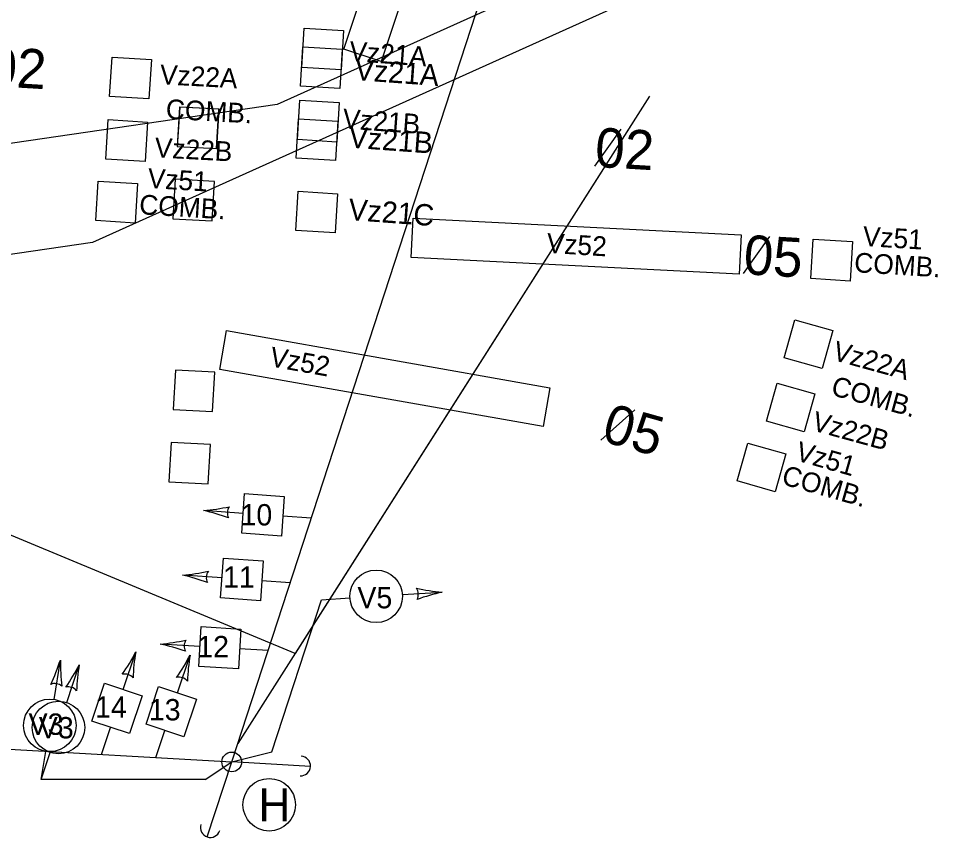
# Model space of a CAD drawing. Extents: x 647787 to 668496, y 640478 to 654412.
# Drawn here: x 662097 to 662238.5, y 647220.2 to 647344.8 of the extents above; entities that cross this region are included whole.
import ezdxf

# ---------------------------------------------------------------- set-up
doc = ezdxf.new("R2010")
doc.units = 0
for name, color, linetype in [('Default', 7, 'Continuous'), ('TEMP_DETECTION ZONE_Stage 2', 7, 'Continuous'), ('TEMP_DETECTION ZONE_STAGE 3', 7, 'Continuous'), ('TEMP_DETECTION_ZONE_STAGE 4', 7, 'Continuous'), ('TEMP_DETECTION_ZONE_STAGE 5', 7, 'Continuous'), ('TEMP_SIGNAL_HEAD_Stage 3', 7, 'Continuous'), ('TEMP_SIGNAL_HEAD_STAGE4', 7, 'Continuous'), ('TEMP_SIGNAL_POLES_STAGE 1B', 7, 'Continuous'), ('TEMP_SIGNAL_POLES_STAGE 3', 7, 'Continuous'), ('TEMP_SIGNAL_POLES_STAGE 4', 7, 'Continuous'), ('TEXT_TEMP_SIGNAL_POLES_STAGE 3', 7, 'Continuous'), ('TEXT_TEMP_SIGNAL_POLES_STAGE 4', 7, 'Continuous')]:
    doc.layers.add(name, color=color, linetype=linetype)

msp = doc.modelspace()

# ---------------------------------------------------------------- linework, layer by layer
at = {"layer": 'Default'}
for p, q in [((662184.78, 647322.37), (662188.82, 647328.03)), ((662207.42, 647306.03), (662211.46, 647311.69)), ((662185.72, 647280.65), (662190.87, 647285.31))]:
    msp.add_line(p, q, dxfattribs=at)
for points in [[(662536.7, 647412.12), (662361.86, 647433.21), (662136.44, 647331.77)], [(662508.55, 647391.12), (662333.71, 647412.21), (662108.29, 647310.77)], [(662508.55, 647391.12), (662333.71, 647412.21), (662108.29, 647310.77)], [(662508.55, 647391.12), (662333.71, 647412.21), (662108.29, 647310.77)], [(662193.11, 647333.04), (662139.14, 647248.2), (661974.83, 647316.48)], [(662193.11, 647333.04), (662130.42, 647234.5)], [(662193.11, 647333.04), (662130.42, 647234.5)], [(662136.44, 647331.77), (661882.02, 647294.61), (661114.4, 647320.89)], [(662108.29, 647310.77), (661853.87, 647273.61), (661086.25, 647299.89)], [(662108.29, 647310.77), (661888.55, 647278.68)], [(662108.29, 647310.77), (661888.55, 647278.68)]]:
    msp.add_lwpolyline(points, dxfattribs=at)
at = {"layer": 'TEMP_DETECTION ZONE_Stage 2'}
msp.add_line((662115.15, 647319.72), (662114.78, 647313.73), dxfattribs=at)
for points in [[(662116.9, 647332.64), (662110.91, 647333), (662111.28, 647338.99), (662117.26, 647338.63)], [(662116.33, 647323.11), (662110.34, 647323.47), (662110.7, 647329.46), (662116.69, 647329.1)], [(662114.78, 647313.73), (662108.8, 647314.09), (662109.16, 647320.08), (662115.15, 647319.72)]]:
    msp.add_lwpolyline(points, close=True, dxfattribs=at)
at = {"layer": 'TEMP_DETECTION ZONE_STAGE 3'}
for points in [[(662152.25, 647338.3), (662146.56, 647340.2), (662162.39, 647387.63), (662168.08, 647385.73)], [(662121.57, 647331.36), (662121.21, 647325.37), (662127.2, 647325.06), (662127.56, 647331.04)], [(662121.57, 647331.36), (662121.21, 647325.37), (662127.2, 647325.06), (662127.56, 647331.04)], [(662121.57, 647331.36), (662121.21, 647325.37), (662127.2, 647325.06), (662127.56, 647331.04)], [(662121.58, 647331.36), (662121.21, 647325.37), (662127.21, 647325.06), (662127.57, 647331.05)], [(662120.91, 647320.38), (662120.55, 647314.39), (662126.54, 647314.08), (662126.9, 647320.06)], [(662120.91, 647320.38), (662120.55, 647314.39), (662126.54, 647314.08), (662126.9, 647320.06)], [(662120.91, 647320.38), (662120.55, 647314.39), (662126.54, 647314.08), (662126.9, 647320.06)], [(662120.91, 647320.38), (662120.55, 647314.39), (662126.54, 647314.08), (662126.9, 647320.07)], [(662156.83, 647308.46), (662157.14, 647314.45), (662207.07, 647311.91), (662206.77, 647305.92)], [(662223.68, 647304.9), (662217.69, 647305.26), (662218.05, 647311.25), (662224.04, 647310.89)]]:
    msp.add_lwpolyline(points, close=True, dxfattribs=at)
at = {"layer": 'TEMP_DETECTION_ZONE_STAGE 4'}
for points in [[(662219.41, 647291.58), (662213.64, 647293.21), (662215.27, 647298.99), (662221.04, 647297.36)], [(662127.67, 647291.45), (662128.72, 647297.35), (662177.95, 647288.65), (662176.91, 647282.74)], [(662120.95, 647291.32), (662120.59, 647285.33), (662126.58, 647285.02), (662126.94, 647291.01)], [(662120.95, 647291.32), (662120.59, 647285.33), (662126.58, 647285.02), (662126.94, 647291.01)], [(662120.95, 647291.32), (662120.59, 647285.33), (662126.58, 647285.02), (662126.94, 647291.01)], [(662120.95, 647291.32), (662120.59, 647285.33), (662126.58, 647285.02), (662126.94, 647291.01)], [(662216.69, 647281.96), (662210.92, 647283.59), (662212.55, 647289.37), (662218.33, 647287.73)], [(662120.29, 647280.34), (662119.93, 647274.35), (662125.92, 647274.04), (662126.28, 647280.03)], [(662120.29, 647280.34), (662119.93, 647274.35), (662125.92, 647274.04), (662126.28, 647280.03)], [(662120.29, 647280.34), (662119.93, 647274.35), (662125.92, 647274.04), (662126.28, 647280.03)], [(662120.29, 647280.34), (662119.93, 647274.35), (662125.92, 647274.04), (662126.28, 647280.03)], [(662212.25, 647272.83), (662206.47, 647274.46), (662208.1, 647280.23), (662213.88, 647278.6)]]:
    msp.add_lwpolyline(points, close=True, dxfattribs=at)
at = {"layer": 'TEMP_DETECTION_ZONE_STAGE 5'}
for points in [[(662146.15, 647337.04), (662140.16, 647337.4), (662140.52, 647343.39), (662146.51, 647343.03)], [(662145.49, 647326.06), (662139.5, 647326.42), (662139.86, 647332.41), (662145.85, 647332.05)]]:
    msp.add_lwpolyline(points, close=True, dxfattribs=at)
at = {"layer": 'TEMP_SIGNAL_HEAD_Stage 3'}
for p, q in [((662131.24, 647269.53), (662125.21, 647269.96)), ((662141.62, 647268.78), (662137.28, 647269.09)), ((662128.03, 647259.7), (662122, 647260.14)), ((662138.41, 647258.95), (662134.07, 647259.27)), ((662135.62, 647233.21), (662143.19, 647256.39)), ((662124.65, 647249.27), (662118.62, 647249.63)), ((662135.04, 647248.64), (662130.7, 647248.9)), ((662112.97, 647242.71), (662114.89, 647248.44)), ((662121.25, 647242.23), (662123.16, 647247.96)), ((662104.37, 647240.74), (662106.29, 647246.49)), ((662109.68, 647232.84), (662111.05, 647236.96)), ((662117.95, 647232.36), (662119.33, 647236.48)), ((662100.48, 647229.04), (662101.85, 647233.15)), ((662129.5, 647231.69), (662135.62, 647233.21)), ((662125.48, 647229.04), (662129.5, 647231.69)), ((662125.48, 647229.04), (662100.48, 647229.04))]:
    msp.add_line(p, q, dxfattribs=at)
for points in [[(662137.5, 647272.12), (662137.06, 647266.07), (662131.02, 647266.5), (662131.45, 647272.55)], [(662134.29, 647262.29), (662133.86, 647256.24), (662127.81, 647256.68), (662128.25, 647262.73)], [(662130.88, 647251.93), (662130.52, 647245.87), (662124.47, 647246.24), (662124.83, 647252.29)], [(662113.93, 647236), (662108.18, 647237.92), (662110.1, 647243.67), (662115.85, 647241.75)], [(662122.2, 647235.52), (662116.45, 647237.44), (662118.37, 647243.19), (662124.12, 647241.27)]]:
    msp.add_lwpolyline(points, close=True, dxfattribs=at)
msp.add_circle((662103.11, 647236.94), 4, dxfattribs=at)
for centre, radius, start, end in [((662122.91, 647299.35), 29.47, 274.4773, 282.2154), ((662118.71, 647241.22), 29.47, 69.5225, 77.2606), ((662130.46, 647269.59), 1.63, 144.0216, 207.7163), ((662119.7, 647289.52), 29.47, 274.4773, 282.2154), ((662115.5, 647231.39), 29.47, 69.5225, 77.2606), ((662127.26, 647259.76), 1.63, 144.0216, 207.7163), ((662115.97, 647278.98), 29.47, 275.1535, 282.8917), ((662123.88, 647249.31), 1.63, 144.6979, 208.3925), ((662112.46, 647220.81), 29.47, 70.1988, 77.9369), ((662088.64, 647261.85), 29.47, 325.2014, 332.9395), ((662143.92, 647243.4), 29.47, 170.1562, 177.8943), ((662096.91, 647261.37), 29.47, 325.2014, 332.9395), ((662152.2, 647242.92), 29.47, 170.1562, 177.8943), ((662080.03, 647259.87), 29.47, 325.255, 332.9931), ((662135.33, 647241.48), 29.47, 170.2106, 177.9488), ((662113.22, 647243.45), 1.63, 39.7005, 103.3952), ((662121.49, 647242.97), 1.63, 39.7005, 103.3952), ((662104.62, 647241.49), 1.63, 39.744, 103.4386)]:
    msp.add_arc(centre, radius, start, end, dxfattribs=at)
at = {"layer": 'TEMP_SIGNAL_HEAD_STAGE4'}
for p, q in [((662131.24, 647269.53), (662125.21, 647269.96)), ((662141.62, 647268.78), (662137.28, 647269.09)), ((662128.03, 647259.7), (662122, 647260.14)), ((662138.41, 647258.95), (662134.07, 647259.27)), ((662155.49, 647257.16), (662161.55, 647257.53)), ((662135.62, 647233.21), (662143.19, 647256.39)), ((662143.19, 647256.39), (662147.51, 647256.66)), ((662124.65, 647249.27), (662118.62, 647249.63)), ((662135.04, 647248.64), (662130.7, 647248.9)), ((662102.44, 647241.21), (662103.4, 647247.2)), ((662100.48, 647229.04), (662101.17, 647233.31)), ((662129.5, 647231.69), (662135.62, 647233.21)), ((662125.48, 647229.04), (662129.5, 647231.69)), ((662125.48, 647229.04), (662100.48, 647229.04))]:
    msp.add_line(p, q, dxfattribs=at)
for points in [[(662137.5, 647272.12), (662137.06, 647266.07), (662131.02, 647266.5), (662131.45, 647272.55)], [(662134.29, 647262.29), (662133.86, 647256.24), (662127.81, 647256.68), (662128.25, 647262.73)], [(662130.88, 647251.93), (662130.52, 647245.87), (662124.47, 647246.24), (662124.83, 647252.29)]]:
    msp.add_lwpolyline(points, close=True, dxfattribs=at)
for centre in [(662151.5, 647256.91), (662101.8, 647237.26)]:
    msp.add_circle(centre, 4, dxfattribs=at)
for centre, radius, start, end in [((662122.91, 647299.35), 29.47, 274.4773, 282.2154), ((662118.71, 647241.22), 29.47, 69.5225, 77.2606), ((662130.46, 647269.59), 1.63, 144.0216, 207.7163), ((662119.7, 647289.52), 29.47, 274.4773, 282.2154), ((662115.5, 647231.39), 29.47, 69.5225, 77.2606), ((662127.26, 647259.76), 1.63, 144.0216, 207.7163), ((662156.29, 647257.2), 1.63, 331.7015, 35.3962), ((662164.14, 647286.89), 29.47, 257.2125, 264.9506), ((662167.76, 647228.72), 29.47, 102.1682, 109.9063), ((662115.97, 647278.98), 29.47, 275.1535, 282.8917), ((662123.88, 647249.31), 1.63, 144.6979, 208.3925), ((662112.46, 647220.81), 29.47, 70.1988, 77.9369), ((662075.33, 647256.18), 29.47, 334.5276, 342.2657), ((662132.87, 647246.93), 29.47, 179.4833, 187.2214), ((662102.56, 647242), 1.63, 49.0166, 112.7112)]:
    msp.add_arc(centre, radius, start, end, dxfattribs=at)
at = {"layer": 'TEMP_SIGNAL_POLES_STAGE 1B'}
for points in [[(662145.95, 647334.21), (662139.96, 647334.57), (662140.32, 647340.56), (662146.31, 647340.2)], [(662145.29, 647323.23), (662139.3, 647323.59), (662139.66, 647329.58), (662145.65, 647329.22)], [(662145.24, 647312.21), (662139.25, 647312.57), (662139.61, 647318.56), (662145.6, 647318.19)]]:
    msp.add_lwpolyline(points, close=True, dxfattribs=at)
at = {"layer": 'TEMP_SIGNAL_POLES_STAGE 3'}
for p, q in [((662129.5, 647231.69), (662176.55, 647375.75)), ((662004.07, 647238.96), (662129.5, 647231.69)), ((662125.78, 647220.28), (662129.5, 647231.69)), ((662141.48, 647230.99), (662129.5, 647231.69))]:
    msp.add_line(p, q, dxfattribs=at)
msp.add_circle((662129.5, 647231.69), 1.5, dxfattribs=at)
for centre, start, end in [((662139.99, 647231.08), 266.682, 86.682), ((662126.24, 647221.71), 161.9139, 341.9139)]:
    msp.add_arc(centre, 1.5, start, end, dxfattribs=at)
at = {"layer": 'TEMP_SIGNAL_POLES_STAGE 4'}
for p, q in [((662129.5, 647231.69), (662176.55, 647375.75)), ((662004.07, 647238.96), (662129.5, 647231.69)), ((662125.78, 647220.28), (662129.5, 647231.69)), ((662141.48, 647230.99), (662129.5, 647231.69))]:
    msp.add_line(p, q, dxfattribs=at)
msp.add_circle((662129.5, 647231.69), 1.5, dxfattribs=at)
for centre, start, end in [((662139.99, 647231.08), 266.682, 86.682), ((662126.24, 647221.71), 161.9139, 341.9139)]:
    msp.add_arc(centre, 1.5, start, end, dxfattribs=at)
at = {"layer": 'TEXT_TEMP_SIGNAL_POLES_STAGE 3'}
msp.add_circle((662135.21, 647225.18), 4, dxfattribs=at)
at = {"layer": 'TEXT_TEMP_SIGNAL_POLES_STAGE 4'}
msp.add_circle((662135.21, 647225.18), 4, dxfattribs=at)

# ---------------------------------------------------------------- texts
at = {"layer": 'Default'}
for s, rotation, p in [('02', 356.6181, (662092.17, 647334.62)), ('02', 356.6181, (662184.72, 647322.29)), ('05', 356.6181, (662207.36, 647305.95)), ('05', 344.3008, (662185.63, 647280.58))]:
    msp.add_text(s, height=6, rotation=rotation, dxfattribs=at).set_placement(p)
at = {"layer": 'TEMP_DETECTION ZONE_Stage 2'}
for s, rotation, p in [('Vz22A', 356.9362, (662118.5, 647334.86)), ('COMB.', 356.9362, (662119.41, 647329.6)), ('Vz22B', 356.9362, (662117.71, 647323.73)), ('Vz51', 356.5267, (662116.64, 647319.07)), ('COMB.', 356.5267, (662115.35, 647315.08))]:
    msp.add_text(s, height=3, rotation=rotation, dxfattribs=at).set_placement(p)
at = {"layer": 'TEMP_DETECTION ZONE_STAGE 3'}
for s, p in [('Vz51', (662225.54, 647310.24)), ('Vz52', (662177.4, 647309.2)), ('COMB.', (662224.24, 647306.25))]:
    msp.add_text(s, height=3, rotation=356.5267, dxfattribs=at).set_placement(p)
at = {"layer": 'TEMP_DETECTION_ZONE_STAGE 4'}
for s, rotation, p in [('Vz22A', 344.6189, (662220.84, 647292.93)), ('Vz52', 349.8762, (662135.14, 647291.95)), ('COMB.', 344.6189, (662220.61, 647287.6)), ('Vz22B', 344.6189, (662217.69, 647282.22)), ('Vz51', 344.2095, (662215.2, 647277.65)), ('COMB.', 344.2095, (662213.08, 647274.02))]:
    msp.add_text(s, height=3, rotation=rotation, dxfattribs=at).set_placement(p)
at = {"layer": 'TEMP_DETECTION_ZONE_STAGE 5'}
for s, p in [('Vz21A', (662147.32, 647338.41)), ('Vz21B', (662146.31, 647328.14))]:
    msp.add_text(s, height=3, rotation=355.8494, dxfattribs=at).set_placement(p)
at = {"layer": 'TEMP_SIGNAL_POLES_STAGE 1B'}
for s, p in [('Vz21A', (662148.17, 647335.5)), ('Vz21B', (662147.24, 647325.22)), ('Vz21C', (662147.19, 647314.2))]:
    msp.add_text(s, height=3.25, rotation=355.8494, dxfattribs=at).set_placement(p)
at = {"layer": 'TEXT_TEMP_SIGNAL_POLES_STAGE 3'}
for s, height, p in [('10', 3.25, (662130.84, 647267.69)), ('11', 3.25, (662128.18, 647258.22)), ('12', 3.25, (662124.25, 647247.63)), ('14', 3.25, (662108.68, 647238.42)), ('13', 3.25, (662116.88, 647238.02)), ('V3', 3.25, (662100.12, 647235.28)), ('H', 5, (662133.58, 647222.68))]:
    msp.add_text(s, height=height, dxfattribs=at).set_placement(p)
at = {"layer": 'TEXT_TEMP_SIGNAL_POLES_STAGE 4'}
for s, height, p in [('10', 3.25, (662130.84, 647267.69)), ('11', 3.25, (662128.18, 647258.22)), ('V5', 3.25, (662148.64, 647255.08)), ('12', 3.25, (662124.25, 647247.63)), ('V3', 3.25, (662098.56, 647235.82)), ('H', 5, (662133.58, 647222.68))]:
    msp.add_text(s, height=height, dxfattribs=at).set_placement(p)

doc.saveas('drawing.dxf')
